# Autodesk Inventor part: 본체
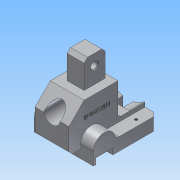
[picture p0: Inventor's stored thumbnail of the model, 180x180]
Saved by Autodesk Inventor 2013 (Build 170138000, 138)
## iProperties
Created: 2016-11
Part Number: 본체
Material: 알루미늄 6061
Document SubType Name: Modeling
Designer: Administrator
Density: 2.71 g/cm^3
Mass: 451.163 g
Surface Area: 309.542 cm^2
Volume: 166.481 cm^3
Author: Administrator
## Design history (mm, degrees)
sketch "스케치1"
  geometry: L1 (0, 0)-(3, 0); L2 (3, 0)-(3, 7); L3 (3, 7)-(23, 7); L4 (23, 7)-(23, 0); L5 (23, 0)-(76, 0); L6 (13, 7)-(13, 15); L7 (0, 0)-(0, 15); L8 (76, 0)-(76, 15); L9 (76, 15)-(30.292, 15); A1 r 13 centre (13, 15) between (25.488, 18.611) and (0, 15); A2 r 5 centre (30.292, 20) between (25.488, 18.611) and (30.292, 15); 1 further point
  constraints: 18 end point, 5 point on circle, 4 perpendicular, 3 tangent, 2 centre point, 2 parallel, 1 coincident, 1 horizontal, 1 midpoint, 1 point on line, 1 vertical
  dimensions: "d11" = 3 distance of L1.start L1.end; "d12" = 7 distance of L1.end L2.end; "d13" = 20 distance of L2.end L3.end; "d14" = 7 distance of L3.end L4.end; "d15" = 63 horizontal distance of L5.end L6.start; "d16" = 15 vertical distance of L6.end L4.end; "d17" = 26 diameter of A1; "d19" = 15 distance of L5.end L8.end; "d20" = 5 radius of A2
extrude "돌출1" new body sketch "스케치1" stored distance "d21" = 70; taper "d22" = 0 deg
chamfer "모따기1" distance "d23" = 5; stored, may be unused: second distance "d24" = 2, angle "d25" = 45 deg
sketch "스케치4"
  geometry: L1 (0, 0)-(0, 15) reference; L2 (30.292, 15)-(76, 15) reference; L3 (76, 15)-(76, 0) reference; L4 (76, 0)-(23, 0) reference; L5 (23, 0)-(23, 7) reference; L6 (23, 7)-(3, 7) reference; L7 (3, 7)-(3, 0) reference; L8 (3, 0)-(0, 0) reference; L9 (-14, 14)-(-14, 40); L10 (-14, 40)-(4, 58); L11 (4, 58)-(44, 58); L12 (44, 58)-(44, 20); L13 (-10, 10)-(76, 10); L14 (76, 10)-(76, 20); L15 (76, 20)-(44, 20); L16 (-14, 14)-(-10, 10); A1 r 13 centre (13, 15) between (25.488, 18.611) and (0, 15) reference; A2 r 5 centre (30.292, 20) between (25.488, 18.611) and (30.292, 15) reference; 1 further point
  constraints: 16 end point, 5 perpendicular, 4 point on line
  dimensions: "d35" = 5 distance between parallel lines of L13 L2; "d36" = 48 vertical distance of L10.end point (-14, 10); "d37" = 30 distance of point (-14, 10) L9.end; "d38" = 45 deg angle of L11 L10; "d40" = 20 distance of L3.end L14.end; "d41" = 4 distance of L9.start point (-14, 10); "d42" = 4 distance of L13.start point (-14, 10) (= d41); "d98" = 90 distance between parallel lines of L3 L9; "d99" = 58 distance between parallel lines of L12 L9
extrude "돌출2" join sketch "스케치4" stored distance "d44" = 40; taper "d45" = 0 deg
sketch "스케치5"
  geometry: L1 (0, 0)-(60, 0) reference; L2 (65, -15)-(65, 0) reference; L3 (-5, 0)-(-5, -15) reference; L4 (30, -42)-(30, 0); L5 (36, -42)-(36, 0); L6 (24, -42)-(24, 0); L7 (36, 0)-(24, 0); A1 r 29 centre (30, -42) between (24, -13.627) and (36, -13.627); 1 further point
  constraints: 8 end point, 4 point on line, 3 parallel, 2 point on circle, 1 centre point, 1 collinear, 1 midpoint
  dimensions: "d46" = 58 diameter of A1; "d48" = 42 distance from line of L1 L4.start; "d49" = 35 distance from line of L4.start L3; "d50" = 12 distance between parallel lines of L6 L5; "d51" = 6 distance between parallel lines of L5 L4
extrude "돌출3" cut sketch "스케치5" distance "d52" = 18; taper "d53" = 0 deg
fillet "모깎기1" dims "d54" = 3
sketch "스케치7"
  geometry: L1 (-15, 45.708)-(-5, 45.708) reference; L2 (-55, 0)-(-55, 45.708) reference; L3 (-65, 45.708)-(-55, 45.708) reference; L4 (-70, 40.708)-(-65, 45.708) reference; L5 (-70, 0)-(-70, 40.708) reference; L6 (-70, 0)-(-55, 0) reference; 3 further points
  constraints: 1 horizontal alignment
  dimensions: "d71" = 55 distance of point (-7.5, 27.708) point (-62.5, 27.708); "d73" = 18 distance from line of L1 point (-7.5, 27.708); "d74" = 7.5 distance from line of L5 point (-62.5, 27.708)
hole "구멍1" sketch "스케치7" at (-7.5, 27.708), (-62.5, 27.708) diameter "d75" = 3.242; stored, may be unused: countersink angle "d79" = 90 deg, drill point angle "d81" = 118 deg; dims "d76" = 50, "d77" = 4, "d78" = 2, "d80" = 50
sketch "스케치8"
  geometry: L1 (-10, 58)-(14, 58) reference; L2 (-15, 58)-(-15, 43) reference; L3 (14, 58)-(26, 58) reference; L4 (20, 58)-(20, 16); C1 r 14.5 at (20, 16)
  constraints: 2 end point, 1 centre point, 1 perpendicular
  dimensions: "d82" = 29 diameter of C1; "d84" = 42 distance from line of L1 L4.end
extrude "돌출5" cut sketch "스케치8" distance "d85" = 7; taper "d86" = 0 deg
sketch "스케치9"
  geometry: C1 r 14.5 at (0, 0) reference; C2 r 10 at (0, 0); 1 further point
  constraints: 1 centre point, 1 coincident
  dimensions: "d87" = 20 diameter of C2
extrude "돌출6" cut sketch "스케치9" stored distance "d89" = 20; taper "d90" = 0 deg
chamfer "모따기3" distance "d91" = 1; stored, may be unused: second distance "d92" = 2, angle "d93" = 45 deg
sketch "스케치10"
  geometry: L1 (-23, 44)-(-58, 44) reference; L2 (-58, 44)-(-58, 4) reference; 2 further points
  constraints: 1 other
  dimensions: "d94" = 25 distance from line of L1 point (-40, 19); "d95" = 18 distance from line of point (-40, 19) L2
feature "엠보싱1" sketch "스케치10" dims "d11" = 3, "d12" = 7, "d13" = 20, "d14" = 7, "d15" = 63, "d16" = 15, "d17" = 26, "d19" = 15, "d20" = 5, "d96" = 0.5, "d97" = 0
sketch "스케치11"
  geometry: L1 (37, 53)-(36, 52) reference; L2 (36, 52)-(-2, 52) reference; L3 (-2, 52)-(4, 58) reference; L4 (4, 58)-(44, 58) reference; L5 (44, 58)-(44, 56.5) reference; L6 (44, 56.5)-(37, 56.5) reference; L7 (37, 56.5)-(37, 53) reference; L8 (0, 10)-(-10, 10) reference; L9 (-10, 10)-(-14, 14) reference; L10 (-14, 14)-(-14, 32) reference; L11 (-14, 32)-(36, 32) reference; L12 (36, 32)-(37, 31) reference; L13 (37, 31)-(37, 27.5) reference; L14 (37, 27.5)-(44, 27.5) reference; L15 (44, 27.5)-(44, 23) reference; L16 (47, 20)-(58, 20) reference; L17 (58, 20)-(58, 0) reference; L18 (58, 0)-(23, 0) reference; L19 (23, 0)-(23, 7) reference; L20 (23, 7)-(3, 7) reference; L21 (3, 7)-(3, 0) reference; L22 (3, 0)-(0, 0) reference; L23 (0, 0)-(0, 10) reference; L24 (14, 58)-(14, 90); L25 (14, 90)-(39, 90); L26 (39, 90)-(39, 58); L27 (44, 56.5)-(44, 27.5) reference; A1 r 3 centre (47, 23) between (44, 23) and (47, 20) reference
  constraints: 6 end point, 2 perpendicular, 2 point on line, 1 parallel
  dimensions: "d100" = 5 distance between parallel lines of L27 L26; "d101" = 25 distance between parallel lines of L24 L26; "d102" = 90 distance between parallel lines of L18 L25
extrude "돌출7" join sketch "스케치11" stored distance "d103" = 20; taper "d104" = 0 deg
chamfer "모따기4" distance "d105" = 4; stored, may be unused: second distance "d106" = 2, angle "d107" = 45 deg
sketch "스케치12"
  geometry: L1 (-86, 14)-(-58, 14) reference; L2 (0, 23)-(0, 71) reference; C1 r 4 at (-77, 26.5); 1 further point
  constraints: 1 centre point
  dimensions: "d111" = 12.5 distance from line of L1 C1.centre; "d112" = 8 diameter of C1; "d113" = 77 distance from line of L2 C1.centre
extrude "돌출8" cut sketch "스케치12" stored distance "d114" = 10; taper "d115" = 0 deg
chamfer "모따기5" distance "d116" = 1; stored, may be unused: second distance "d117" = 2, angle "d118" = 45 deg
node "솔리드1"
node "투영된 루프1"
node "절단 모서리 투영1"
node "절단 모서리 투영3"
